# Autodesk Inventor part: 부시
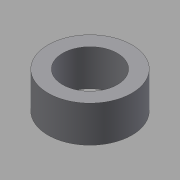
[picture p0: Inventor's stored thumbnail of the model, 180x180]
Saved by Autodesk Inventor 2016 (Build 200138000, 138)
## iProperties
Created: 2015-09
Part Number: 부시
Document SubType Name: Modeling
Designer: mduedu
Density: 1 g/cm^3
Material: 스테인리스강
Appearance: 기본값
Author: mduedu
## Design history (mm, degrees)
node "작업 평면1"
node "작업 평면2"
sketch "스케치1"
  geometry: C1 r 7.5 at (0, 0); C2 r 11.5 at (0, 0); 1 further point
  constraints: 2 centre point, 2 coincident
  dimensions: "d0" = 15 diameter of C1; "d1" = 23 diameter of C2
extrude "돌출1" new body sketch "스케치1" stored distance "d2" = 9.85; taper "d3" = 0 deg
node "솔리드1"
